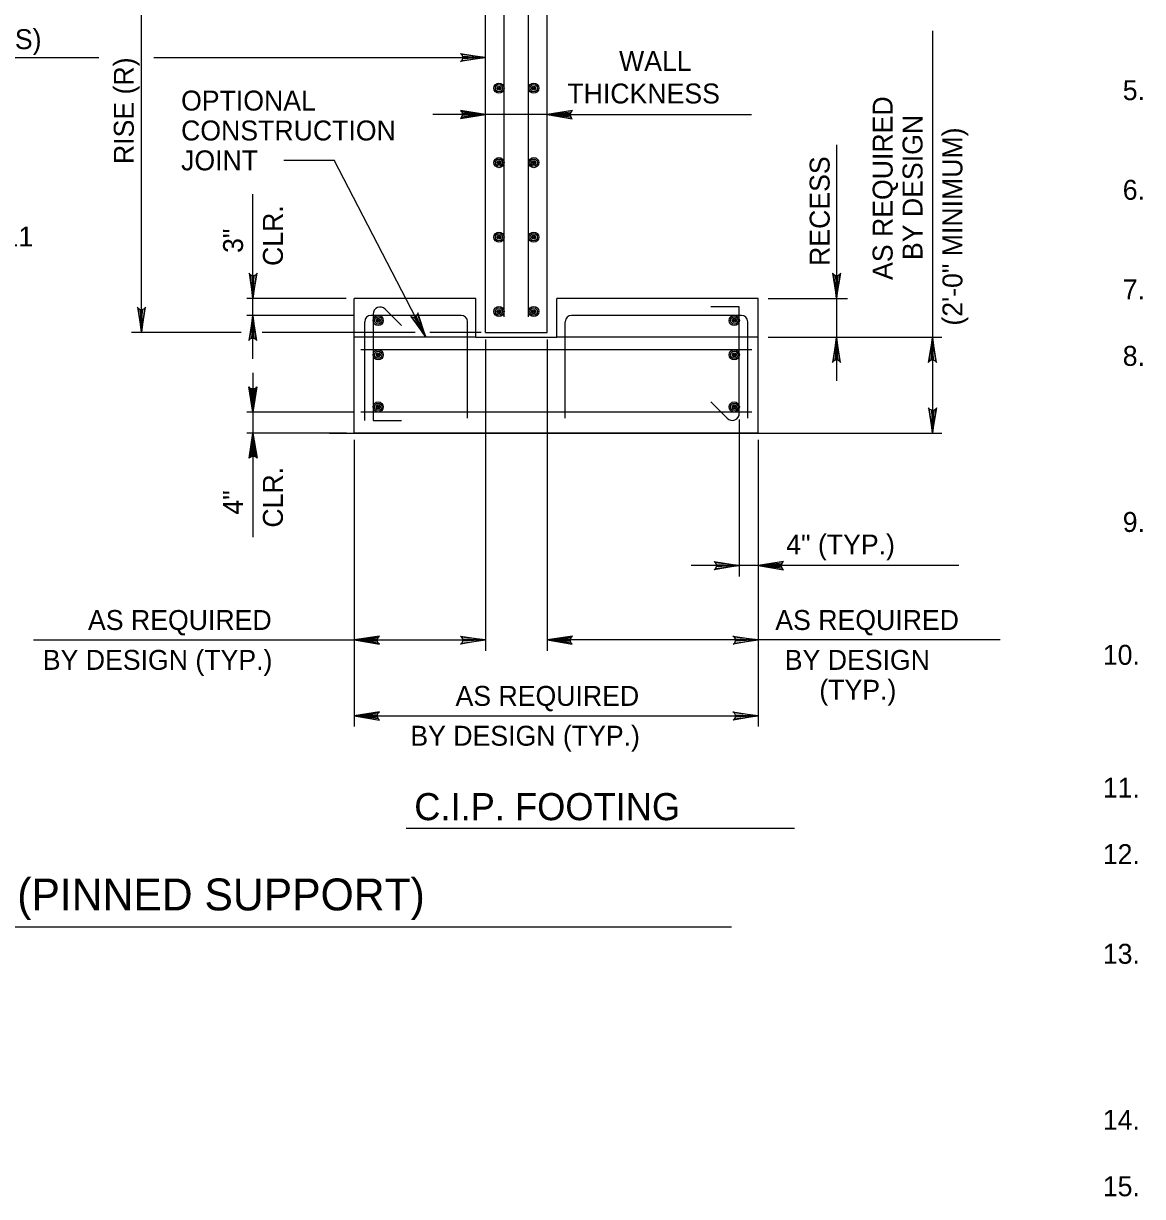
# Model space of a CAD drawing. Extents: x 641328 to 643024, y 298283 to 300065.
# Drawn here: x 641508.5 to 641676.9, y 299774.9 to 299951.5 of the extents above; entities that cross this region are included whole.
import ezdxf

# ---------------------------------------------------------------- set-up
doc = ezdxf.new("R2010")
doc.units = 0
doc.layers.add('2', color=7, linetype='Continuous')

msp = doc.modelspace()

# ---------------------------------------------------------------- linework, layer by layer
at = {"layer": '2'}
for p, q in [((641587.3, 299904.97), (641587.3, 299987.4)), ((641526.24, 299904.97), (641526.24, 299974.52)), ((641578.05, 299904.97), (641578.05, 299968.83)), ((641580.83, 299907.34), (641580.83, 299969.35)), ((641584.52, 299907.34), (641584.52, 299969.35)), ((641645.3, 299950.38), (641645.3, 299904.26)), ((641574.44, 299946.81), (641574.25, 299946.97)), ((641574.25, 299946.97), (641578.05, 299946.38)), ((641574.44, 299946.81), (641574.58, 299946.54)), ((641578.05, 299946.38), (641574.44, 299946.81)), ((641438.8, 299946.38), (641519.83, 299946.38)), ((641528.11, 299946.38), (641578.05, 299946.38)), ((641578.05, 299946.38), (641574.26, 299945.74)), ((641574.26, 299945.74), (641574.45, 299945.92)), ((641574.45, 299945.92), (641578.05, 299946.38)), ((641574.58, 299946.18), (641574.45, 299945.92)), ((641574.58, 299946.54), (641578.05, 299946.38)), ((641574.58, 299946.54), (641574.58, 299946.18)), ((641578.05, 299946.38), (641574.58, 299946.18)), ((641578.05, 299946.38), (641574.58, 299946.36)), ((641578.05, 299937.77), (641574.26, 299938.4)), ((641574.26, 299938.4), (641574.45, 299938.23)), ((641574.58, 299937.96), (641574.45, 299938.23)), ((641574.45, 299938.23), (641578.05, 299937.77)), ((641578.05, 299937.77), (641574.58, 299937.96)), ((641574.58, 299937.6), (641574.58, 299937.96)), ((641591.1, 299938.36), (641587.3, 299937.77)), ((641587.3, 299937.77), (641590.91, 299938.2)), ((641590.77, 299937.93), (641587.3, 299937.77)), ((641590.91, 299938.2), (641590.77, 299937.93)), ((641590.77, 299937.93), (641590.77, 299937.57)), ((641590.91, 299938.2), (641591.1, 299938.36)), ((641587.3, 299937.77), (641570.1, 299937.77)), ((641574.25, 299937.18), (641578.05, 299937.77)), ((641574.44, 299937.34), (641574.25, 299937.18)), ((641578.05, 299937.77), (641574.44, 299937.34)), ((641574.44, 299937.34), (641574.58, 299937.6)), ((641578.05, 299937.77), (641574.58, 299937.78)), ((641574.58, 299937.6), (641578.05, 299937.77)), ((641587.3, 299937.77), (641618.05, 299937.77)), ((641587.3, 299937.77), (641590.77, 299937.57)), ((641590.9, 299937.31), (641587.3, 299937.77)), ((641587.3, 299937.77), (641591.09, 299937.13)), ((641587.3, 299937.77), (641590.77, 299937.75)), ((641590.77, 299937.57), (641590.9, 299937.31)), ((641591.09, 299937.13), (641590.9, 299937.31)), ((641630.86, 299933.19), (641630.86, 299910.07)), ((641547.67, 299930.88), (641555.25, 299930.88)), ((641569.05, 299904.26), (641555.25, 299930.88)), ((641543.04, 299910.07), (641543.04, 299925.77)), ((641542.61, 299913.68), (641542.45, 299913.87)), ((641542.45, 299913.87), (641543.04, 299910.07)), ((641542.61, 299913.68), (641542.88, 299913.55)), ((641543.04, 299910.07), (641542.61, 299913.68)), ((641542.88, 299913.55), (641543.04, 299910.07)), ((641542.88, 299913.55), (641543.24, 299913.54)), ((641543.04, 299910.07), (641543.68, 299913.87)), ((641543.5, 299913.67), (641543.04, 299910.07)), ((641543.04, 299910.07), (641543.06, 299913.55)), ((641543.04, 299910.07), (641543.24, 299913.54)), ((641543.04, 299900.99), (641543.04, 299913.35)), ((641543.24, 299913.54), (641543.5, 299913.67)), ((641543.68, 299913.87), (641543.5, 299913.67)), ((641630.43, 299913.68), (641630.27, 299913.87)), ((641630.27, 299913.87), (641630.86, 299910.07)), ((641630.43, 299913.68), (641630.7, 299913.55)), ((641630.86, 299910.07), (641630.43, 299913.68)), ((641630.7, 299913.55), (641630.86, 299910.07)), ((641630.7, 299913.55), (641631.06, 299913.54)), ((641630.86, 299910.07), (641631.5, 299913.87)), ((641631.32, 299913.67), (641630.86, 299910.07)), ((641630.86, 299910.07), (641630.88, 299913.55)), ((641630.86, 299910.07), (641631.06, 299913.54)), ((641631.06, 299913.54), (641631.32, 299913.67)), ((641631.5, 299913.87), (641631.32, 299913.67)), ((641557.06, 299910.07), (641542.13, 299910.07)), ((641558.27, 299889.82), (641558.27, 299910.07)), ((641576.6, 299910.07), (641558.27, 299910.07)), ((641576.6, 299904.26), (641576.6, 299910.07)), ((641619.08, 299910.07), (641588.76, 299910.07)), ((641588.76, 299904.26), (641588.76, 299910.07)), ((641619.08, 299889.82), (641619.08, 299910.07)), ((641620.58, 299910.07), (641632.53, 299910.07)), ((641630.86, 299910.07), (641630.86, 299897.71)), ((641525.81, 299908.58), (641525.65, 299908.77)), ((641525.65, 299908.77), (641526.24, 299904.97)), ((641525.81, 299908.58), (641526.07, 299908.44)), ((641526.24, 299904.97), (641525.81, 299908.58)), ((641526.07, 299908.44), (641526.24, 299904.97)), ((641526.07, 299908.44), (641526.43, 299908.44)), ((641526.24, 299904.97), (641526.87, 299908.76)), ((641526.69, 299908.57), (641526.24, 299904.97)), ((641526.24, 299904.97), (641526.43, 299908.44)), ((641526.24, 299904.97), (641526.25, 299908.44)), ((641526.43, 299908.44), (641526.69, 299908.57)), ((641526.87, 299908.76), (641526.69, 299908.57)), ((641565.4, 299906.03), (641562.95, 299908.48)), ((641567.85, 299907.92), (641567.79, 299907.66)), ((641569.05, 299904.26), (641567.85, 299907.92)), ((641616.23, 299908.8), (641611.95, 299908.8)), ((641616.23, 299892.8), (641616.23, 299908.8)), ((641558.11, 299907.54), (641542.13, 299907.54)), ((641543.04, 299907.54), (641542.41, 299903.75)), ((641542.58, 299903.94), (641543.04, 299907.54)), ((641543.04, 299907.54), (641542.84, 299904.07)), ((641543.04, 299907.54), (641543.03, 299904.07)), ((641543.21, 299904.07), (641543.04, 299907.54)), ((641543.04, 299907.54), (641543.47, 299903.93)), ((641543.63, 299903.74), (641543.04, 299907.54)), ((641559.86, 299891.73), (641559.86, 299906.59)), ((641574.37, 299907.54), (641560.8, 299907.54)), ((641561.12, 299907.73), (641561.12, 299891.73)), ((641567, 299907.26), (641566.77, 299907.36)), ((641566.77, 299907.36), (641569.05, 299904.26)), ((641567, 299907.26), (641567.29, 299907.26)), ((641569.05, 299904.26), (641567, 299907.26)), ((641567.29, 299907.26), (641567.62, 299907.43)), ((641567.29, 299907.26), (641569.05, 299904.26)), ((641569.05, 299904.26), (641567.46, 299907.35)), ((641567.62, 299907.43), (641567.79, 299907.66)), ((641569.05, 299904.26), (641567.62, 299907.43)), ((641567.79, 299907.66), (641569.05, 299904.26)), ((641575.33, 299892.07), (641575.33, 299906.59)), ((641590.03, 299892.07), (641590.03, 299906.59)), ((641616.54, 299907.54), (641590.98, 299907.54)), ((641617.49, 299892.07), (641617.49, 299906.59)), ((641541.24, 299904.97), (641524.74, 299904.97)), ((641567.43, 299904.97), (641544.4, 299904.97)), ((641577.36, 299904.97), (641569.67, 299904.97)), ((641542.41, 299903.75), (641542.58, 299903.94)), ((641542.84, 299904.07), (641542.58, 299903.94)), ((641543.21, 299904.07), (641542.84, 299904.07)), ((641543.47, 299903.93), (641543.21, 299904.07)), ((641543.47, 299903.93), (641543.63, 299903.74)), ((641576.6, 299904.26), (641558.27, 299904.26)), ((641576.6, 299904.26), (641588.76, 299904.26)), ((641578.05, 299903.93), (641578.05, 299857.05)), ((641587.3, 299903.93), (641587.3, 299857.05)), ((641619.08, 299904.26), (641588.76, 299904.26)), ((641620.58, 299904.26), (641646.71, 299904.26)), ((641630.86, 299904.26), (641630.23, 299900.47)), ((641630.4, 299900.66), (641630.86, 299904.26)), ((641630.86, 299904.26), (641630.67, 299900.79)), ((641630.86, 299904.26), (641630.85, 299900.79)), ((641631.03, 299900.79), (641630.86, 299904.26)), ((641630.86, 299904.26), (641631.29, 299900.65)), ((641631.45, 299900.46), (641630.86, 299904.26)), ((641645.3, 299904.26), (641644.67, 299900.47)), ((641644.85, 299900.66), (641645.3, 299904.26)), ((641645.3, 299904.26), (641645.11, 299900.79)), ((641645.3, 299904.26), (641645.29, 299900.79)), ((641645.3, 299904.26), (641645.3, 299889.82)), ((641645.47, 299900.79), (641645.3, 299904.26)), ((641645.3, 299904.26), (641645.73, 299900.65)), ((641645.89, 299900.46), (641645.3, 299904.26)), ((641618.1, 299902.36), (641559.25, 299902.36)), ((641630.67, 299900.79), (641630.4, 299900.66)), ((641631.03, 299900.79), (641630.67, 299900.79)), ((641631.29, 299900.65), (641631.03, 299900.79)), ((641645.11, 299900.79), (641644.85, 299900.66)), ((641645.47, 299900.79), (641645.11, 299900.79)), ((641645.73, 299900.65), (641645.47, 299900.79)), ((641630.23, 299900.47), (641630.4, 299900.66)), ((641631.29, 299900.65), (641631.45, 299900.46)), ((641644.67, 299900.47), (641644.85, 299900.66)), ((641645.73, 299900.65), (641645.89, 299900.46)), ((641543.04, 299898.91), (641543.04, 299885.92)), ((641543.04, 299892.99), (641542.41, 299896.78)), ((641542.41, 299896.78), (641542.58, 299896.59)), ((641542.84, 299896.46), (641542.58, 299896.59)), ((641542.58, 299896.59), (641543.04, 299892.99)), ((641543.04, 299892.99), (641542.84, 299896.46)), ((641543.21, 299896.46), (641542.84, 299896.46)), ((641543.04, 299892.99), (641543.03, 299896.46)), ((641543.63, 299896.79), (641543.04, 299892.99)), ((641543.04, 299892.99), (641543.47, 299896.6)), ((641543.21, 299896.46), (641543.04, 299892.99)), ((641543.47, 299896.6), (641543.21, 299896.46)), ((641543.47, 299896.6), (641543.63, 299896.79)), ((641611.95, 299894.5), (641614.4, 299892.05)), ((641558.11, 299892.99), (641542.13, 299892.99)), ((641618.1, 299892.99), (641559.25, 299892.99)), ((641644.87, 299893.43), (641644.71, 299893.62)), ((641644.71, 299893.62), (641645.3, 299889.82)), ((641644.87, 299893.43), (641645.14, 299893.3)), ((641645.3, 299889.82), (641644.87, 299893.43)), ((641645.14, 299893.3), (641645.3, 299889.82)), ((641645.14, 299893.3), (641645.5, 299893.29)), ((641645.3, 299889.82), (641645.94, 299893.62)), ((641645.76, 299893.42), (641645.3, 299889.82)), ((641645.3, 299889.82), (641645.32, 299893.3)), ((641645.3, 299889.82), (641645.5, 299893.29)), ((641645.5, 299893.29), (641645.76, 299893.42)), ((641645.94, 299893.62), (641645.76, 299893.42)), ((641561.12, 299891.73), (641565.4, 299891.73)), ((641616.23, 299891.89), (641616.23, 299868.25)), ((641557.13, 299889.82), (641542.13, 299889.82)), ((641542.45, 299886.02), (641543.04, 299889.82)), ((641543.04, 299889.82), (641542.61, 299886.21)), ((641542.88, 299886.35), (641543.04, 299889.82)), ((641543.04, 299889.82), (641543.24, 299886.35)), ((641543.5, 299886.22), (641543.04, 299889.82)), ((641543.04, 299889.82), (641543.68, 299886.03)), ((641543.04, 299889.82), (641543.06, 299886.35)), ((641543.04, 299889.82), (641543.04, 299874.16)), ((641554.57, 299889.82), (641622.78, 299889.82)), ((641619.08, 299889.82), (641558.27, 299889.82)), ((641558.27, 299888.79), (641558.27, 299845.64)), ((641619.08, 299888.79), (641619.08, 299845.64)), ((641620.58, 299889.82), (641646.71, 299889.82)), ((641542.61, 299886.21), (641542.45, 299886.02)), ((641542.61, 299886.21), (641542.88, 299886.35)), ((641542.88, 299886.35), (641543.24, 299886.35)), ((641543.24, 299886.35), (641543.5, 299886.22)), ((641543.68, 299886.03), (641543.5, 299886.22)), ((641649.27, 299869.88), (641609, 299869.88)), ((641612.62, 299870.31), (641612.43, 299870.47)), ((641612.43, 299870.47), (641616.23, 299869.88)), ((641616.23, 299869.88), (641612.44, 299869.24)), ((641612.44, 299869.24), (641612.63, 299869.42)), ((641612.62, 299870.31), (641612.76, 299870.04)), ((641616.23, 299869.88), (641612.62, 299870.31)), ((641612.63, 299869.42), (641616.23, 299869.88)), ((641612.76, 299869.68), (641612.63, 299869.42)), ((641612.76, 299870.04), (641616.23, 299869.88)), ((641612.76, 299870.04), (641612.76, 299869.68)), ((641616.23, 299869.88), (641612.76, 299869.68)), ((641616.23, 299869.88), (641612.76, 299869.86)), ((641622.88, 299870.47), (641619.08, 299869.88)), ((641619.08, 299869.88), (641622.69, 299870.31)), ((641622.55, 299870.04), (641619.08, 299869.88)), ((641619.08, 299869.88), (641622.55, 299869.68)), ((641622.67, 299869.42), (641619.08, 299869.88)), ((641619.08, 299869.88), (641622.87, 299869.24)), ((641619.08, 299869.88), (641622.55, 299869.86)), ((641622.69, 299870.31), (641622.55, 299870.04)), ((641622.55, 299870.04), (641622.55, 299869.68)), ((641622.55, 299869.68), (641622.67, 299869.42)), ((641622.87, 299869.24), (641622.67, 299869.42)), ((641622.69, 299870.31), (641622.88, 299870.47)), ((641510.01, 299858.68), (641558.27, 299858.68)), ((641562.08, 299859.27), (641558.27, 299858.68)), ((641558.27, 299858.68), (641561.88, 299859.11)), ((641561.75, 299858.85), (641558.27, 299858.68)), ((641558.27, 299858.68), (641578.05, 299858.68)), ((641558.27, 299858.68), (641561.74, 299858.48)), ((641561.87, 299858.22), (641558.27, 299858.68)), ((641558.27, 299858.68), (641562.07, 299858.05)), ((641558.27, 299858.68), (641561.75, 299858.66)), ((641561.75, 299858.85), (641561.74, 299858.48)), ((641561.74, 299858.48), (641561.87, 299858.22)), ((641561.88, 299859.11), (641561.75, 299858.85)), ((641561.88, 299859.11), (641562.08, 299859.27)), ((641574.44, 299859.11), (641574.25, 299859.27)), ((641574.25, 299859.27), (641578.05, 299858.68)), ((641578.05, 299858.68), (641574.26, 299858.05)), ((641574.44, 299859.11), (641574.58, 299858.85)), ((641578.05, 299858.68), (641574.44, 299859.11)), ((641574.45, 299858.22), (641578.05, 299858.68)), ((641574.58, 299858.48), (641574.45, 299858.22)), ((641574.58, 299858.85), (641578.05, 299858.68)), ((641574.58, 299858.85), (641574.58, 299858.48)), ((641578.05, 299858.68), (641574.58, 299858.48)), ((641578.05, 299858.68), (641574.58, 299858.66)), ((641591.1, 299859.27), (641587.3, 299858.68)), ((641587.3, 299858.68), (641590.91, 299859.11)), ((641590.77, 299858.85), (641587.3, 299858.68)), ((641619.08, 299858.68), (641587.3, 299858.68)), ((641587.3, 299858.68), (641590.77, 299858.48)), ((641590.9, 299858.22), (641587.3, 299858.68)), ((641587.3, 299858.68), (641591.09, 299858.05)), ((641587.3, 299858.68), (641590.77, 299858.66)), ((641590.91, 299859.11), (641590.77, 299858.85)), ((641590.77, 299858.85), (641590.77, 299858.48)), ((641590.77, 299858.48), (641590.9, 299858.22)), ((641590.91, 299859.11), (641591.1, 299859.27)), ((641615.47, 299859.11), (641615.27, 299859.27)), ((641615.27, 299859.27), (641619.08, 299858.68)), ((641619.08, 299858.68), (641615.28, 299858.05)), ((641615.47, 299859.11), (641615.6, 299858.85)), ((641619.08, 299858.68), (641615.47, 299859.11)), ((641615.48, 299858.22), (641619.08, 299858.68)), ((641615.61, 299858.48), (641615.48, 299858.22)), ((641615.6, 299858.85), (641619.08, 299858.68)), ((641615.6, 299858.85), (641615.61, 299858.48)), ((641619.08, 299858.68), (641615.6, 299858.66)), ((641619.08, 299858.68), (641615.61, 299858.48)), ((641655.47, 299858.68), (641619.08, 299858.68)), ((641562.07, 299858.05), (641561.87, 299858.22)), ((641574.26, 299858.05), (641574.45, 299858.22)), ((641591.09, 299858.05), (641590.9, 299858.22)), ((641615.28, 299858.05), (641615.48, 299858.22)), ((641562.08, 299847.85), (641558.27, 299847.26)), ((641561.88, 299847.69), (641562.08, 299847.85)), ((641615.47, 299847.69), (641615.27, 299847.85)), ((641615.27, 299847.85), (641619.08, 299847.26)), ((641558.27, 299847.26), (641561.88, 299847.69)), ((641561.75, 299847.43), (641558.27, 299847.26)), ((641558.27, 299847.26), (641619.08, 299847.26)), ((641558.27, 299847.26), (641561.74, 299847.07)), ((641561.87, 299846.8), (641558.27, 299847.26)), ((641558.27, 299847.26), (641562.07, 299846.63)), ((641558.27, 299847.26), (641561.75, 299847.25)), ((641561.75, 299847.43), (641561.74, 299847.07)), ((641561.74, 299847.07), (641561.87, 299846.8)), ((641561.88, 299847.69), (641561.75, 299847.43)), ((641562.07, 299846.63), (641561.87, 299846.8)), ((641619.08, 299847.26), (641615.28, 299846.63)), ((641615.28, 299846.63), (641615.48, 299846.8)), ((641615.47, 299847.69), (641615.6, 299847.43)), ((641619.08, 299847.26), (641615.47, 299847.69)), ((641615.48, 299846.8), (641619.08, 299847.26)), ((641615.61, 299847.07), (641615.48, 299846.8)), ((641615.6, 299847.43), (641619.08, 299847.26)), ((641615.6, 299847.43), (641615.61, 299847.07)), ((641619.08, 299847.26), (641615.6, 299847.25)), ((641619.08, 299847.26), (641615.61, 299847.07)), ((641624.54, 299830.3), (641566.08, 299830.3)), ((641402.88, 299815.49), (641615.06, 299815.49))]:
    msp.add_line(p, q, dxfattribs=at)
msp.add_lwpolyline([(641578.05, 299904.97), (641587.3, 299904.97)], dxfattribs=at)
for centre, radius in [((641580.06, 299941.74), 0.763), ((641580.06, 299941.74), 0.545), ((641580.06, 299941.74), 0.298), ((641580.06, 299941.74), 0.15), ((641580.06, 299941.74), 0.0644), ((641585.29, 299941.74), 0.763), ((641585.29, 299941.74), 0.545), ((641585.29, 299941.74), 0.298), ((641585.29, 299941.74), 0.15), ((641585.29, 299941.74), 0.0644), ((641580.06, 299930.53), 0.763), ((641580.06, 299930.53), 0.545), ((641580.06, 299930.53), 0.298), ((641585.29, 299930.53), 0.763), ((641585.29, 299930.53), 0.545), ((641585.29, 299930.53), 0.298), ((641580.06, 299930.53), 0.15), ((641580.06, 299930.53), 0.0644), ((641585.29, 299930.53), 0.15), ((641585.29, 299930.53), 0.0644), ((641580.06, 299919.32), 0.763), ((641580.06, 299919.32), 0.545), ((641580.06, 299919.32), 0.298), ((641580.06, 299919.32), 0.15), ((641580.06, 299919.32), 0.0644), ((641585.29, 299919.32), 0.763), ((641585.29, 299919.32), 0.545), ((641585.29, 299919.32), 0.298), ((641585.29, 299919.32), 0.15), ((641585.29, 299919.32), 0.0644), ((641580.06, 299908.11), 0.763), ((641580.06, 299908.11), 0.545), ((641580.06, 299908.11), 0.298), ((641580.06, 299908.11), 0.15), ((641580.06, 299908.11), 0.0644), ((641585.29, 299908.11), 0.763), ((641585.29, 299908.11), 0.545), ((641585.29, 299908.11), 0.298), ((641585.29, 299908.11), 0.15), ((641585.29, 299908.11), 0.0644), ((641561.89, 299906.78), 0.763), ((641561.89, 299906.78), 0.545), ((641561.89, 299906.78), 0.298), ((641561.89, 299906.78), 0.15), ((641561.89, 299906.78), 0.0644), ((641615.47, 299906.78), 0.763), ((641615.47, 299906.78), 0.545), ((641615.47, 299906.78), 0.298), ((641615.47, 299906.78), 0.15), ((641615.47, 299906.78), 0.0644), ((641561.89, 299901.59), 0.763), ((641561.89, 299901.59), 0.545), ((641561.89, 299901.59), 0.298), ((641561.89, 299901.59), 0.15), ((641561.89, 299901.59), 0.0644), ((641615.47, 299901.59), 0.763), ((641615.47, 299901.59), 0.545), ((641615.47, 299901.59), 0.298), ((641615.47, 299901.59), 0.15), ((641615.47, 299901.59), 0.0644), ((641561.89, 299893.75), 0.763), ((641561.89, 299893.75), 0.545), ((641561.89, 299893.75), 0.298), ((641561.89, 299893.75), 0.15), ((641561.89, 299893.75), 0.0644), ((641615.47, 299893.75), 0.763), ((641615.47, 299893.75), 0.545), ((641615.47, 299893.75), 0.298), ((641615.47, 299893.75), 0.15), ((641615.47, 299893.75), 0.0644)]:
    msp.add_circle(centre, radius, dxfattribs=at)
for centre, radius, start, end in [((641562.19, 299907.73), 1.07, 45, 180), ((641560.81, 299906.59), 0.953, 90, 180), ((641574.37, 299906.59), 0.953, 0, 90), ((641590.98, 299906.59), 0.953, 90, 180), ((641616.54, 299906.59), 0.953, 0, 90), ((641615.16, 299892.8), 1.07, 225, 0)]:
    msp.add_arc(centre, radius, start, end, dxfattribs=at)

# ---------------------------------------------------------------- texts
for s, height, p in [('SPAN (S)', 3, (641493.83, 299947.62)), ('WALL', 3, (641598.13, 299944.34)), ('OPTIONAL', 3, (641532.22, 299938.37)), ('THICKNESS', 3, (641590.35, 299939.44)), ('5.', 3, (641673.93, 299939.94)), ('CONSTRUCTION ', 3, (641532.22, 299933.87)), ('JOINT', 3, (641532.22, 299929.37)), ('6.', 3, (641673.93, 299924.94)), ('SEE DRAWING NOTE 11', 3, (641463.61, 299917.91)), ('7.', 3, (641673.93, 299909.94)), ('8.', 3, (641673.93, 299899.94)), ('9.', 3, (641673.93, 299874.94)), ('4" (TYP.)', 3, (641623.29, 299871.55)), ('AS REQUIRED ', 3, (641518.21, 299860.18)), ('AS REQUIRED', 3, (641621.64, 299860.18)), ('BY DESIGN (TYP.)', 3, (641511.41, 299854.18)), ('BY DESIGN ', 3, (641623.07, 299854.18)), ('10.', 3, (641670.93, 299854.94)), ('AS REQUIRED ', 3, (641573.52, 299848.76)), ('(TYP.)', 3, (641628.27, 299849.68)), ('BY DESIGN (TYP.)', 3, (641566.72, 299842.76)), ('11.', 3, (641670.93, 299834.94)), ('C.I.P. FOOTING', 4.08, (641567.31, 299831.55)), ('12.', 3, (641670.93, 299824.94)), ('TYPICAL RIGID FRAME SECTION (PINNED SUPPORT)', 4.8, (641404.85, 299817.97)), ('13.', 3, (641670.93, 299809.94)), ('14.', 3, (641670.93, 299784.94)), ('15.', 3, (641670.93, 299774.94))]:
    msp.add_text(s, height=height, dxfattribs=at).set_placement(p)
for s, p in [('RISE (R)', (641525.1, 299930.32)), ('AS REQUIRED ', (641639.3, 299912.87)), ('BY DESIGN', (641643.8, 299915.87)), ('(2\'-0" MINIMUM)', (641649.8, 299906)), ('RECESS', (641629.82, 299914.98)), ('CLR.', (641547.54, 299914.98)), ('3" ', (641541.54, 299916.94)), ('CLR.', (641547.54, 299875.59)), ('4" ', (641541.54, 299877.55))]:
    msp.add_text(s, height=3, rotation=90, dxfattribs=at).set_placement(p)

doc.saveas('drawing.dxf')
